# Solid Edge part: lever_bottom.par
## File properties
Author: vinurabandara
Template: iso metric part.par
Last saved by: Nimesh.N
Revision: 2
Application: Solid Edge
Username: Nimesh.N
Density: 7750.000 kg/m^3
Accuracy: 0.990
Material: Stainless Steel, 420
Face Style: Steel
Fill Style: ANSI32(Steel)
Virtual Style: ANSI32(Steel)
Grouping: Metals\Steel
LibraryName: Materials
Coef. of Thermal Exp: 1e-05
Thermal Conductivity: 25.0
Specific Heat: 502.0
Modulus of Elasticity: 199947953000.0
Poisson's Ratio: 0.29
Yield Stress: 344737850.0
Ultimate Stress: 655001915.0
Elongation: 0.0
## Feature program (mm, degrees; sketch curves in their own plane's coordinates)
sketch for "unnamed Protrusion 1" plane through (0, 0, 0) normal (0, -1, 0) x-axis (1, 0, 0)
  circle centre (0, 0) radius 6
extrude "unnamed Protrusion 1" add finite 250 along +normal
thread "Thread_1"  ThreadDepth = 30 mm
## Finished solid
Body 1: solid body, 4 faces, 3 edges, 0 vertices.
  Faces by surface: cylinder 2, plane 2
  Edges by curve: circle 3
Bounding box of the edges (mm): 12.000 x 250.000 x 12.000, from (-6, -250, -6) to (6, 0, 6).
Cylindrical faces by radius (mm): R6 x2
Planar faces by outward normal: +y 1, -y 1
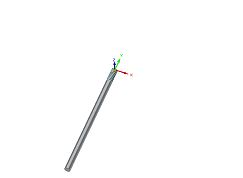
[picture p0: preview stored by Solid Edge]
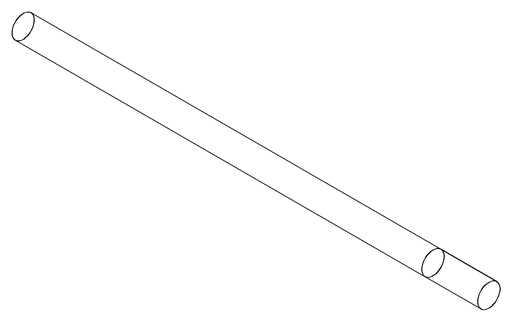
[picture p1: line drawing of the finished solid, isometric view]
